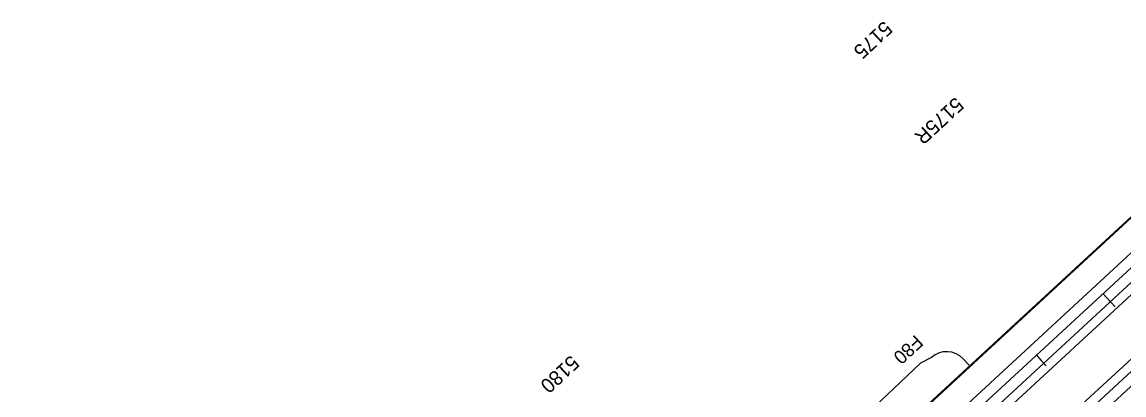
# Model space of a CAD drawing. Extents: x 2160877 to 2175861, y 601747 to 617724.
# Drawn here: x 2170763 to 2171979, y 613431 to 613842 of the extents above; entities that cross this region are included whole.
import ezdxf

# ---------------------------------------------------------------- set-up
doc = ezdxf.new("R2010")
doc.units = 0
for name, color, linetype in [('RD_HC_Cl', 7, 'Continuous'), ('RD_HC_CL_Rel', 7, 'Continuous'), ('RD_HC_Data_Tic', 7, 'Continuous'), ('RD_HC_Data_Tic_Rel', 7, 'Continuous'), ('RD_HC_TX_Rel_Sta50', 7, 'Continuous'), ('RD_HC_TX_StaOther', 7, 'Continuous'), ('RD_PD_CstnLmt', 7, 'Continuous'), ('RD_PD_CstnLmt_TX', 7, 'Continuous'), ('RD_PD_Final_LnLine', 7, 'Continuous'), ('RD_PD_Final_TrvlWay', 7, 'Continuous'), ('RD_PD_MedBWall', 7, 'Continuous')]:
    doc.layers.add(name, color=color, linetype=linetype)

msp = doc.modelspace()

# ---------------------------------------------------------------- linework, layer by layer
at = {"layer": 'RD_HC_Cl'}
for p, q in [((2172207.3, 613775.1), (2163672.2, 605893.8)), ((2172272.5, 613704.6), (2163737.4, 605823.3))]:
    msp.add_line(p, q, dxfattribs=at)
at = {"layer": 'RD_HC_CL_Rel'}
for p, q in [((2172207.3, 613775.1), (2171340.7, 612974.9)), ((2172272.5, 613704.6), (2170771.4, 612318.6))]:
    msp.add_line(p, q, dxfattribs=at)
at = {"layer": 'RD_HC_Data_Tic'}
for p, q in [((2171955.5, 613542.6), (2171966.3, 613530.8)), ((2171882, 613474.7), (2171887.4, 613468.9))]:
    msp.add_line(p, q, dxfattribs=at)
at = {"layer": 'RD_HC_Data_Tic_Rel'}
for p, q in [((2171955.5, 613542.6), (2171969, 613527.9)), ((2171882, 613474.7), (2171892.9, 613463))]:
    msp.add_line(p, q, dxfattribs=at)
at = {"layer": 'RD_PD_CstnLmt'}
for p, q in [((2171766.2, 613472), (2171754.2, 613465.7)), ((2171807.8, 613463.6), (2171801.4, 613470.5)), ((2171754.2, 613465.7), (2171681.6, 613397)), ((2171754.2, 613465.7), (2171754.2, 613465.7))]:
    msp.add_line(p, q, dxfattribs=at)
msp.add_arc((2171783.1, 613453.5), 25, 42.7195, 132.3521, dxfattribs=at)
at = {"layer": 'RD_PD_Final_LnLine'}
for p, q in [((2172199.2, 613784), (2171332.6, 612983.8)), ((2172215.5, 613766.3), (2171348.9, 612966.1)), ((2172264.3, 613713.4), (2170763.3, 612327.4))]:
    msp.add_line(p, q, dxfattribs=at)
at = {"layer": 'RD_PD_Final_TrvlWay'}
for p, q in [((2172222.2, 613759), (2171355.7, 612958.8)), ((2172257.5, 613720.8), (2170756.5, 612334.7))]:
    msp.add_line(p, q, dxfattribs=at)
at = {"layer": 'RD_PD_MedBWall'}
for p, q in [((2172075.1, 613709.3), (2171312.7, 613005.3)), ((2172075.8, 613708.6), (2171313.4, 613004.6))]:
    msp.add_line(p, q, dxfattribs=at)

# ---------------------------------------------------------------- texts
at = {"layer": 'RD_HC_TX_Rel_Sta50'}
msp.add_text('5175R', height=16, rotation=222.7195, dxfattribs=at).set_placement((2171792.7, 613760.1))
at = {"layer": 'RD_HC_TX_StaOther'}
for s, p in [('5175', (2171714, 613844.1)), ('5180', (2171368.6, 613475.5))]:
    msp.add_text(s, height=16, rotation=222.7195, dxfattribs=at).set_placement(p)
at = {"layer": 'RD_PD_CstnLmt_TX'}
msp.add_text('F80', height=15, rotation=222.7195, dxfattribs=at).set_placement((2171748.4, 613497.9))

doc.saveas('drawing.dxf')
